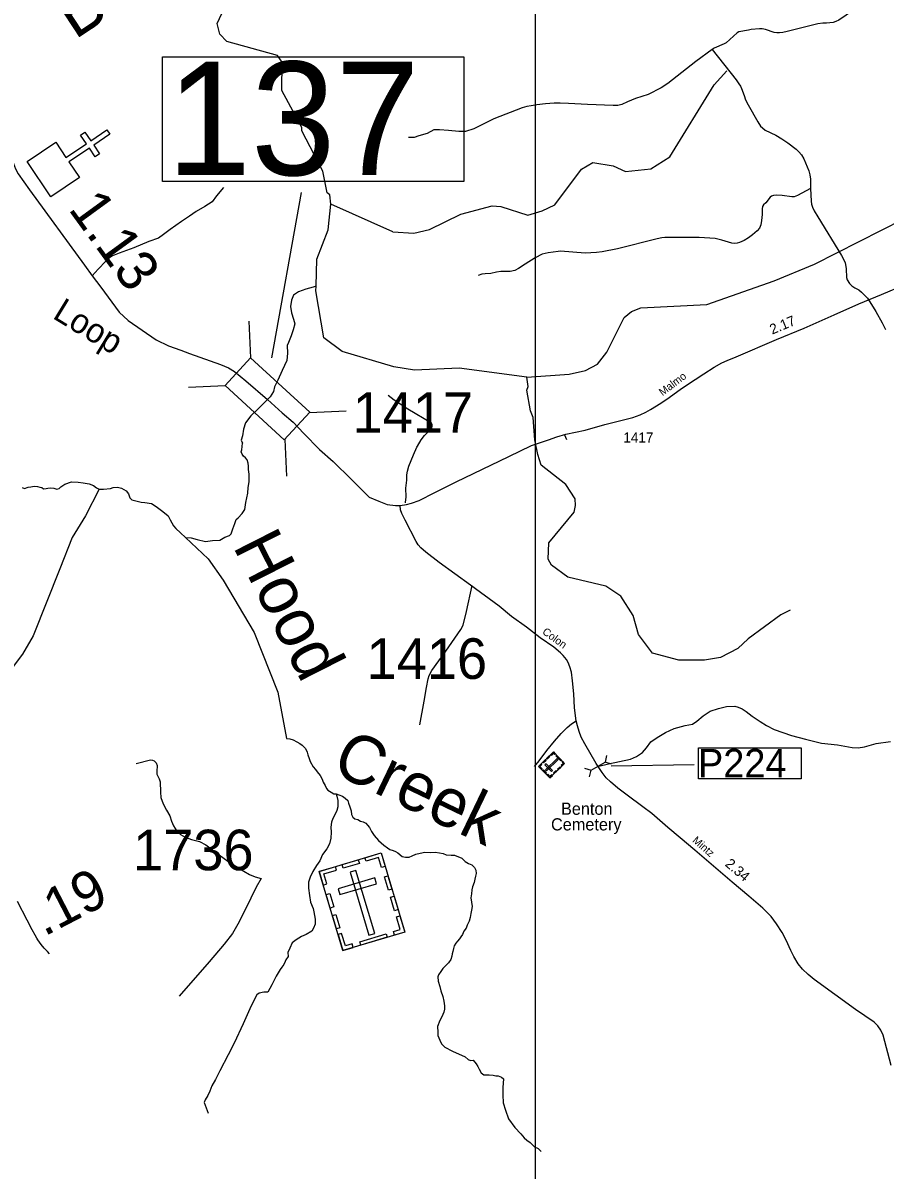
# Model space of a CAD drawing. Extents: x 2225501 to 2309677, y 165449 to 227696.
# Drawn here: x 2259935 to 2270573, y 174218 to 188364 of the extents above; entities that cross this region are included whole.
import ezdxf

# ---------------------------------------------------------------- set-up
doc = ezdxf.new("R2010")
doc.units = 0
for name, color, linetype in [('E_RDY_CMT_EOP', 7, 'Continuous'), ('Exist Vegetation Text', 7, 'Continuous'), ('MARK ENDS WORD SYMBOL CELL', 7, 'Continuous'), ('Old_Level_3', 7, 'Continuous'), ('Old_Level_33', 7, 'Continuous'), ('Old_Level_44', 7, 'Continuous'), ('Old_Level_50', 7, 'Continuous'), ('Old_Level_52', 7, 'Continuous'), ('P_HYD_Drainage_Notes_Label', 7, 'Continuous'), ('P_HYD_Endwall_838_01_18_Dia_Single-Top_CELL', 7, 'Continuous'), ('P_HYD_Pipe_Pipe_Removal', 7, 'Continuous'), ('P_RDY_Dimension_Text', 7, 'Continuous'), ('Prop Mkg Solid Yellow Edge Line', 7, 'Continuous'), ('Prop Support', 7, 'Continuous'), ('Scratch_Level_1', 7, 'Continuous'), ('Scratch_Level_5', 7, 'Continuous'), ('Typical Terminator CELL', 7, 'Continuous')]:
    doc.layers.add(name, color=color, linetype=linetype)

msp = doc.modelspace()

# ---------------------------------------------------------------- linework, layer by layer
at = {"layer": 'Old_Level_3'}
msp.add_line((2266619, 183285), (2266640, 183226), dxfattribs=at)
for points in [[(2270185, 188522), (2270002, 188399), (2269966, 188382), (2269933, 188370), (2269852, 188360), (2269806, 188361), (2269743, 188354), (2269364, 188259), (2269312, 188248), (2269271, 188244), (2269236, 188243), (2269204, 188247), (2269098, 188282), (2269058, 188292), (2269023, 188292), (2268922, 188285), (2268888, 188277), (2268768, 188255), (2268746, 188244), (2268612, 188120), (2268587, 188105), (2268464, 188053), (2268438, 188037)], [(2268438, 188037), (2268237, 187889), (2267893, 187617), (2267810, 187562), (2267648, 187483), (2267494, 187433), (2267393, 187391), (2267324, 187357), (2267274, 187347), (2267216, 187347), (2266900, 187358), (2266666, 187372), (2266562, 187375), (2266488, 187373), (2266382, 187366), (2266276, 187355), (2266204, 187344), (2266152, 187332), (2266096, 187316), (2265745, 187180), (2265497, 187058), (2265394, 187027), (2265315, 187026), (2265185, 187038), (2265073, 187044), (2265005, 187044), (2264924, 187001), (2264818, 186970), (2264762, 186951), (2264694, 186951)], [(2268438, 188037), (2268737, 187662), (2268770, 187615), (2268788, 187585), (2268803, 187555), (2268836, 187468), (2268851, 187416), (2268882, 187355), (2269002, 187143), (2269037, 187093), (2269059, 187070), (2269093, 187042), (2269225, 186979), (2269299, 186936), (2269374, 186885), (2269477, 186807), (2269510, 186776), (2269541, 186736), (2269570, 186687), (2269632, 186542), (2269645, 186490), (2269651, 186438), (2269652, 186324)], [(2262409, 186335), (2262325, 186232), (2262271, 186159), (2262179, 186100), (2262074, 186040), (2261990, 185983), (2261890, 185916), (2261752, 185818), (2261671, 185756), (2261609, 185710), (2261490, 185667), (2261303, 185589), (2261122, 185526), (2261041, 185491), (2261006, 185472), (2260957, 185426), (2260863, 185326), (2260791, 185246)], [(2269652, 186324), (2269492, 186235), (2269452, 186221), (2269422, 186220), (2269302, 186235), (2269234, 186241), (2269198, 186236), (2269172, 186228), (2269154, 186214), (2269101, 186146), (2269074, 186120), (2269062, 186102), (2269057, 186072), (2269056, 186000), (2269049, 185928), (2269038, 185873), (2269023, 185835), (2268995, 185801), (2268935, 185750), (2268889, 185715), (2268836, 185683), (2268778, 185657), (2268746, 185648), (2268710, 185644), (2268680, 185647), (2268559, 185685), (2268477, 185704), (2268278, 185720), (2267923, 185720), (2267855, 185717), (2267819, 185714), (2267759, 185703), (2267271, 185580), (2267080, 185541), (2267014, 185532), (2266874, 185525), (2266568, 185548), (2266538, 185547), (2266416, 185529), (2266342, 185511), (2266255, 185467), (2266132, 185388), (2266048, 185335), (2266004, 185313), (2265947, 185300), (2265881, 185300), (2265833, 185300), (2265780, 185291), (2265710, 185273), (2265640, 185269), (2265596, 185265), (2265552, 185251)], [(2269652, 186324), (2269659, 186168), (2269665, 186128), (2269678, 186091), (2269699, 186049), (2269744, 185972), (2270035, 185497), (2270082, 185410), (2270092, 185330), (2270097, 185224), (2270104, 185196), (2270133, 185149), (2270161, 185123), (2270198, 185098), (2270247, 185071), (2270281, 185045), (2270320, 185009), (2270354, 184970), (2270385, 184925)], [(2270385, 184925), (2270457, 184806), (2270535, 184666), (2270577, 184582)], [(2264657, 182447), (2264657, 182449), (2264662, 182521), (2264660, 182629), (2264670, 182726), (2264671, 182790), (2264679, 182836), (2264698, 182898), (2264754, 183039), (2264796, 183134), (2264802, 183144), (2264848, 183224), (2264890, 183275), (2264891, 183277), (2264982, 183372), (2264985, 183390), (2264985, 183406), (2264981, 183420), (2264975, 183430), (2264685, 183603), (2264514, 183712), (2264441, 183770)], [(2264832, 179710), (2264885, 179999), (2264913, 180169), (2264935, 180276), (2264948, 180318), (2264981, 180379), (2265155, 180617), (2265336, 180884), (2265366, 180937), (2265409, 181105), (2265477, 181425)], [(2267041, 179197), (2267160, 179227), (2267433, 179286), (2267506, 179318), (2267578, 179369), (2267630, 179424), (2267683, 179497), (2267760, 179553), (2267865, 179613), (2267972, 179665), (2268105, 179700), (2268195, 179717), (2268252, 179752), (2268329, 179820), (2268416, 179878), (2268517, 179908), (2268615, 179933), (2268719, 179938), (2268761, 179928), (2268811, 179907), (2268858, 179874), (2268933, 179814), (2269030, 179748), (2269108, 179701), (2269206, 179651), (2269418, 179575), (2269589, 179530), (2269788, 179484), (2269984, 179460), (2270167, 179428), (2270239, 179423), (2270319, 179438), (2270462, 179479), (2270638, 179501)], [(2266247, 179195), (2266305, 179263), (2266399, 179390), (2266493, 179506), (2266575, 179600), (2266649, 179675), (2266702, 179720), (2266762, 179759)], [(2261331, 179233), (2261509, 179275), (2261533, 179273), (2261553, 179264), (2261577, 179240), (2261592, 179208), (2261586, 179132), (2261589, 179098), (2261617, 179044), (2261630, 179005), (2261631, 178877), (2261638, 178811), (2261667, 178733), (2261706, 178655), (2261747, 178588), (2261768, 178520), (2261794, 178461), (2261833, 178399), (2261880, 178357), (2261938, 178322), (2262014, 178293), (2262113, 178270), (2262193, 178229), (2262310, 178139), (2262461, 178028), (2262659, 177903), (2262731, 177862), (2262800, 177832), (2262876, 177813), (2262811, 177707), (2262680, 177437), (2262585, 177252), (2262522, 177137), (2262416, 177002), (2262234, 176786), (2261863, 176362)]]:
    msp.add_lwpolyline(points, dxfattribs=at)
at = {"layer": 'Old_Level_33'}
for points in [[(2259355, 188119), (2259430, 187933), (2259522, 187620), (2259608, 187337), (2259668, 187105), (2259737, 186885), (2259808, 186664), (2259842, 186567), (2259875, 186505), (2260016, 186307), (2260694, 185377), (2260791, 185246), (2260894, 185106), (2261122, 184798), (2261235, 184695), (2261579, 184456), (2261731, 184382), (2261883, 184329), (2261988, 184289), (2262373, 184152), (2262470, 184111), (2262544, 184064), (2262687, 183949), (2262952, 183720)], [(2264588, 182415), (2264667, 182427), (2264730, 182441), (2264825, 182475), (2265019, 182572), (2265282, 182704), (2265496, 182807), (2265931, 183017), (2266208, 183154), (2266420, 183225), (2266522, 183259), (2266633, 183294), (2266872, 183343), (2267113, 183412), (2267461, 183498), (2267549, 183533), (2267619, 183564), (2267679, 183599), (2267804, 183676), (2267910, 183747), (2268062, 183855), (2268230, 183968), (2268338, 184037), (2268465, 184119), (2268560, 184171), (2268623, 184202), (2268735, 184246), (2269234, 184459), (2269573, 184600), (2269943, 184763), (2270248, 184899), (2270530, 185015), (2270820, 185139)], [(2262952, 183720), (2263135, 183554), (2263271, 183439), (2263399, 183302), (2263596, 183104), (2263761, 182956), (2263988, 182733), (2264207, 182516), (2264326, 182465), (2264428, 182427), (2264532, 182413), (2264588, 182415)], [(2270647, 175508), (2270551, 175883), (2270522, 175944), (2270484, 175997), (2270437, 176042), (2270208, 176198), (2269698, 176568), (2269623, 176628), (2269554, 176695), (2269501, 176762), (2269445, 176851), (2269410, 176924), (2269351, 177051), (2269301, 177146), (2269235, 177255), (2269166, 177346), (2269064, 177449), (2268893, 177597), (2268687, 177770), (2268225, 178161), (2268045, 178315), (2267892, 178444), (2267693, 178616), (2267584, 178699), (2267392, 178842), (2267276, 178929), (2267184, 179005), (2267131, 179054), (2267082, 179122), (2267006, 179232), (2266868, 179473), (2266824, 179558), (2266797, 179628), (2266777, 179697), (2266762, 179759), (2266741, 179919), (2266731, 180089), (2266716, 180253), (2266702, 180358), (2266684, 180425), (2266664, 180475), (2266640, 180512), (2266601, 180562), (2266569, 180595), (2266484, 180665), (2266318, 180781), (2266147, 180914), (2265965, 181046), (2265810, 181173), (2265456, 181432), (2265070, 181711), (2264908, 181836), (2264845, 181891), (2264813, 181929), (2264788, 181968), (2264651, 182233), (2264608, 182316), (2264594, 182358), (2264588, 182415)]]:
    msp.add_lwpolyline(points, dxfattribs=at)
at = {"layer": 'Old_Level_44'}
for p, q in [((2266945, 179150), (2267117, 179249)), ((2267137, 179330), (2267117, 179249)), ((2267197, 179225), (2267117, 179249)), ((2266865, 179174), (2266945, 179150)), ((2266926, 179069), (2266945, 179150))]:
    msp.add_line(p, q, dxfattribs=at)
at = {"layer": 'Old_Level_50'}
msp.add_lwpolyline([(2260264, 176885), (2260237, 176913), (2260196, 176954), (2260161, 176998), (2260119, 177058), (2260107, 177079), (2260085, 177116), (2260048, 177181), (2259986, 177299), (2259867, 177528)], dxfattribs=at)
at = {"layer": 'Old_Level_52'}
msp.add_line((2267191, 179203), (2268218, 179220), dxfattribs=at)
msp.add_lwpolyline([(2268271, 179425), (2269537, 179425), (2269537, 179041), (2268271, 179041)], close=True, dxfattribs=at)
at = {"layer": 'P_HYD_Drainage_Notes_Label'}
for p, q in [((2262723, 184685), (2262742, 184233)), ((2261977, 183872), (2262429, 183892)), ((2263472, 183561), (2263924, 183581)), ((2263166, 183228), (2263185, 182775))]:
    msp.add_line(p, q, dxfattribs=at)
msp.add_lwpolyline([(2262742, 184233), (2263473, 183563), (2263160, 183222), (2262429, 183892)], close=True, dxfattribs=at)
at = {"layer": 'P_HYD_Endwall_838_01_18_Dia_Single-Top_CELL'}
msp.add_line((2263008, 184233), (2263370, 186275), dxfattribs=at)
msp.add_lwpolyline([(2261658, 187945), (2265374, 187945), (2265374, 186408), (2261658, 186408)], close=True, dxfattribs=at)
at = {"layer": 'P_HYD_Pipe_Pipe_Removal'}
msp.add_lwpolyline([(2266254, 165449), (2309677, 165449), (2309677, 209697), (2266254, 209697)], close=True, dxfattribs=at)
at = {"layer": 'Prop Mkg Solid Yellow Edge Line'}
for points in [[(2266438, 179055), (2266298, 179196), (2266480, 179375), (2266619, 179233)], [(2266389, 179270), (2266358, 179240), (2266350, 179248), (2266381, 179278)], [(2266382, 179153), (2266396, 179140), (2266540, 179282), (2266527, 179295)], [(2266436, 179316), (2266405, 179286), (2266397, 179294), (2266428, 179324)], [(2266503, 179352), (2266495, 179344), (2266479, 179359), (2266451, 179331), (2266443, 179339), (2266480, 179375)], [(2266571, 179266), (2266511, 179327), (2266519, 179335), (2266579, 179274)], [(2266596, 179257), (2266588, 179249), (2266603, 179233), (2266575, 179205), (2266583, 179197), (2266619, 179233)], [(2266329, 179227), (2266337, 179219), (2266314, 179196), (2266343, 179167), (2266335, 179160), (2266298, 179196)], [(2266386, 179107), (2266350, 179144), (2266358, 179152), (2266394, 179115)], [(2266458, 179131), (2266471, 179145), (2266389, 179228), (2266375, 179215)], [(2266469, 179085), (2266461, 179093), (2266438, 179071), (2266410, 179099), (2266402, 179092), (2266438, 179055)], [(2266522, 179137), (2266491, 179107), (2266483, 179115), (2266514, 179145)], [(2266570, 179184), (2266539, 179154), (2266531, 179162), (2266562, 179192)], [(2263591, 177899), (2264354, 178128), (2264647, 177153), (2263884, 176924)], [(2264404, 177962), (2264361, 177949), (2264323, 178072), (2264168, 178026), (2264155, 178068), (2264354, 178128)], [(2263875, 177984), (2264073, 178044), (2264087, 178000), (2263888, 177941)], [(2263641, 177733), (2263684, 177746), (2263647, 177869), (2263803, 177916), (2263790, 177959), (2263591, 177899)], [(2263826, 177685), (2263847, 177614), (2264298, 177749), (2264277, 177821)], [(2264043, 177912), (2263971, 177891), (2264204, 177114), (2264276, 177135)], [(2264444, 177669), (2264395, 177835), (2264438, 177848), (2264488, 177682)], [(2263726, 177449), (2263676, 177615), (2263720, 177628), (2263770, 177462)], [(2264520, 177416), (2264470, 177582), (2264514, 177595), (2264564, 177430)], [(2263804, 177191), (2263754, 177357), (2263797, 177370), (2263847, 177205)], [(2264520, 177115), (2264507, 177159), (2264591, 177184), (2264544, 177339), (2264587, 177352), (2264647, 177153)], [(2264011, 176962), (2263998, 177006), (2263913, 176981), (2263867, 177135), (2263824, 177123), (2263884, 176924)], [(2264091, 177034), (2264416, 177131), (2264429, 177088), (2264104, 176990)]]:
    msp.add_lwpolyline(points, close=True, dxfattribs=at)
at = {"layer": 'Prop Support'}
msp.add_line((2264497, 185790), (2263732, 186131), dxfattribs=at)
for points in [[(2264497, 185790), (2264760, 185773), (2264951, 185815), (2265340, 186005), (2265723, 186109), (2265831, 186100), (2266165, 185995), (2266340, 186048), (2266497, 186123), (2266826, 186560), (2266967, 186645), (2267217, 186604), (2267368, 186533), (2267684, 186566), (2267916, 186712), (2268466, 187600), (2268622, 187774)], [(2266250, 183223), (2266230, 183498), (2266196, 183580), (2266152, 183837), (2266168, 183879), (2266151, 183995)], [(2269403, 181124), (2269287, 181064), (2268882, 180770), (2268758, 180651), (2268543, 180540), (2268343, 180505), (2268026, 180504), (2267701, 180593), (2267532, 180822), (2267463, 181056), (2267311, 181296), (2267126, 181420), (2266659, 181531), (2266458, 181679), (2266415, 181752), (2266422, 181952), (2266735, 182333), (2266751, 182415), (2266750, 182497), (2266632, 182673), (2266330, 182912), (2266287, 183044), (2266250, 183223)]]:
    msp.add_lwpolyline(points, dxfattribs=at)
at = {"layer": 'Scratch_Level_5'}
msp.add_lwpolyline([(2260339, 186893), (2260466, 186704), (2260719, 186875), (2260647, 186981), (2260700, 187016), (2260772, 186910), (2260971, 187045), (2261007, 186992), (2260808, 186857), (2260879, 186751), (2260826, 186715), (2260755, 186821), (2260502, 186651), (2260631, 186460), (2260278, 186221), (2259986, 186654)], close=True, dxfattribs=at)
at = {"layer": 'Typical Terminator CELL'}
msp.add_line((2261877, 182076), (2261939, 182019), dxfattribs=at)
for points in [[(2263732, 186131), (2263723, 186246), (2263689, 186270), (2263637, 186536), (2263375, 187033), (2263375, 187076), (2263129, 187533), (2263135, 187881), (2263076, 187964), (2262450, 188134), (2262366, 188227), (2262331, 188359), (2262446, 188603), (2262669, 188877), (2262676, 188986), (2262625, 189144), (2262457, 189328), (2262455, 189544), (2262644, 189829), (2262693, 189979), (2262707, 190343), (2262829, 190662), (2262827, 190944), (2262750, 191162)], [(2266151, 183995), (2266675, 184034), (2266875, 184079), (2267024, 184155), (2267139, 184303), (2267352, 184732), (2267442, 184806), (2267559, 184850), (2268375, 184893), (2269205, 185182), (2269703, 185388), (2271079, 186090), (2271635, 186305), (2271991, 186567), (2272248, 186703), (2272472, 186745), (2272806, 186683), (2272982, 186525), (2273050, 186409), (2273094, 186169), (2273204, 185960), (2273255, 185903), (2273548, 185783)], [(2263551, 185116), (2263563, 185452), (2263702, 185813), (2263732, 186131)], [(2263551, 185116), (2263518, 185104), (2263471, 185092), (2263426, 185082), (2263337, 185050), (2263273, 185007), (2263248, 184945), (2263238, 184866), (2263247, 184790), (2263272, 184712), (2263291, 184654), (2263270, 184580), (2263243, 184504), (2263212, 184425), (2263196, 184385), (2263198, 184291), (2263191, 184200), (2263132, 184077), (2263082, 183958), (2263038, 183877), (2263028, 183818), (2262985, 183752), (2262928, 183697), (2262837, 183606), (2262747, 183519), (2262680, 183433), (2262657, 183354), (2262642, 183272), (2262629, 183220), (2262646, 183183)], [(2264512, 184122), (2263872, 184314), (2263646, 184480), (2263550, 185062), (2263551, 185116)], [(2266151, 183995), (2265317, 184106), (2264767, 184084), (2264512, 184122)], [(2261939, 182019), (2262011, 182014), (2262083, 181994), (2262186, 181970), (2262275, 181980), (2262365, 181984), (2262426, 182021), (2262482, 182045), (2262506, 182065), (2262524, 182127), (2262548, 182193), (2262566, 182241), (2262590, 182263), (2262638, 182313), (2262674, 182365), (2262686, 182451), (2262708, 182565), (2262712, 182635), (2262728, 182705), (2262726, 182745), (2262726, 182801), (2262720, 182857), (2262718, 182899), (2262714, 182937), (2262700, 182975), (2262682, 182999), (2262658, 183021), (2262640, 183045), (2262628, 183073), (2262634, 183099), (2262646, 183183)], [(2259925, 182637), (2259954, 182621), (2259999, 182641), (2260034, 182645), (2260074, 182651), (2260115, 182649), (2260142, 182641), (2260166, 182635), (2260188, 182619), (2260220, 182621), (2260244, 182625), (2260280, 182633), (2260318, 182627), (2260352, 182613), (2260382, 182621), (2260404, 182645), (2260452, 182677), (2260532, 182703), (2260616, 182701), (2260678, 182691), (2260750, 182681), (2260806, 182661), (2260842, 182633), (2260874, 182613)], [(2260874, 182613), (2260927, 182613), (2261014, 182623), (2261049, 182635), (2261102, 182641), (2261151, 182627), (2261209, 182593), (2261237, 182557), (2261255, 182509), (2261279, 182485), (2261329, 182469), (2261395, 182453), (2261439, 182451), (2261521, 182437), (2261579, 182401), (2261661, 182341), (2261727, 182287), (2261753, 182235), (2261793, 182163), (2261823, 182130), (2261877, 182076)], [(2260874, 182613), (2260706, 182286), (2260544, 182017), (2260389, 181633), (2260063, 180807), (2259931, 180580), (2259338, 179801), (2258945, 178939), (2258648, 178538), (2258028, 178052), (2257338, 177786), (2256682, 177563)], [(2261939, 182019), (2262222, 181756), (2262406, 181493), (2262788, 180847), (2263078, 180110), (2263186, 179540), (2263227, 179537), (2263271, 179523), (2263315, 179499), (2263350, 179479), (2263382, 179457), (2263420, 179415), (2263440, 179371), (2263450, 179339), (2263466, 179295), (2263478, 179255), (2263514, 179191), (2263544, 179157), (2263566, 179129), (2263602, 179083), (2263626, 179037), (2263640, 179003), (2263666, 178961), (2263682, 178923), (2263696, 178903), (2263740, 178879), (2263770, 178859), (2263798, 178857)], [(2263798, 178857), (2263808, 178828), (2263820, 178774), (2263822, 178716), (2263822, 178696), (2263808, 178652), (2263790, 178616), (2263758, 178552), (2263742, 178508), (2263732, 178448), (2263739, 178384), (2263735, 178310), (2263717, 178240), (2263685, 178179), (2263633, 178108), (2263599, 178030), (2263559, 177974), (2263513, 177898), (2263479, 177828), (2263459, 177770), (2263457, 177696), (2263471, 177602), (2263482, 177520), (2263516, 177445), (2263523, 177402), (2263539, 177312), (2263539, 177250), (2263522, 177199), (2263498, 177162), (2263431, 177124), (2263373, 177099), (2263307, 177058), (2263257, 177019), (2263230, 176954), (2263205, 176899), (2263208, 176853), (2263180, 176811), (2263170, 176789), (2263155, 176753), (2263129, 176719), (2263110, 176691), (2263058, 176608), (2263007, 176504), (2262956, 176412), (2262909, 176411), (2262851, 176398), (2262822, 176377), (2262751, 176245), (2262653, 176023), (2262540, 175782), (2262467, 175640), (2262365, 175443), (2262309, 175336), (2262267, 175258), (2262239, 175192), (2262217, 175138), (2262185, 175083), (2262170, 175049), (2262219, 174918)], [(2263798, 178857), (2263834, 178845), (2263876, 178829), (2263912, 178802), (2263944, 178776), (2263950, 178744), (2263968, 178696), (2263984, 178646), (2263990, 178602), (2264004, 178568), (2264030, 178548), (2264068, 178540), (2264102, 178522), (2264134, 178512), (2264166, 178494), (2264186, 178472), (2264212, 178442), (2264234, 178392), (2264270, 178344), (2264322, 178280), (2264386, 178224), (2264432, 178192), (2264464, 178172), (2264502, 178158), (2264532, 178146), (2264562, 178128)], [(2264562, 178128), (2264616, 178086), (2264656, 178076), (2264702, 178075), (2264738, 178093), (2264784, 178114), (2264838, 178126), (2264892, 178137), (2264960, 178134), (2265022, 178136), (2265074, 178131), (2265120, 178121), (2265158, 178106), (2265220, 178101), (2265259, 178099), (2265351, 178062), (2265392, 178021), (2265434, 177999), (2265474, 177980), (2265505, 177948), (2265523, 177918), (2265527, 177876), (2265520, 177842), (2265512, 177804), (2265503, 177764), (2265483, 177710), (2265472, 177674), (2265468, 177624), (2265463, 177574), (2265471, 177522), (2265476, 177466), (2265470, 177422), (2265461, 177380), (2265455, 177332), (2265440, 177288), (2265416, 177237), (2265403, 177199), (2265375, 177163), (2265358, 177121), (2265338, 177094), (2265322, 177068), (2265298, 177042), (2265277, 177014), (2265257, 176982), (2265247, 176949), (2265240, 176915), (2265232, 176883), (2265226, 176855), (2265213, 176815), (2265187, 176775), (2265153, 176741), (2265116, 176704), (2265092, 176666), (2265063, 176626), (2265053, 176601), (2265059, 176548), (2265078, 176480), (2265091, 176426), (2265116, 176358), (2265130, 176300), (2265137, 176243), (2265137, 176203), (2265128, 176163), (2265102, 176106), (2265077, 176064), (2265050, 175988), (2265054, 175920), (2265055, 175878), (2265078, 175820), (2265098, 175774), (2265139, 175733), (2265237, 175684), (2265392, 175614), (2265429, 175582), (2265457, 175569), (2265489, 175571), (2265527, 175529), (2265546, 175494), (2265566, 175460), (2265589, 175416), (2265621, 175393), (2265689, 175391), (2265735, 175386), (2265769, 175378), (2265798, 175379), (2265840, 175365), (2265866, 175343), (2265857, 175237), (2265856, 175147), (2265861, 175045), (2265890, 174958), (2265928, 174848), (2266005, 174743), (2266080, 174664), (2266121, 174615), (2266151, 174585), (2266193, 174557), (2266248, 174506), (2266294, 174483), (2266331, 174447)]]:
    msp.add_lwpolyline(points, dxfattribs=at)

# ---------------------------------------------------------------- texts
at = {"layer": 'E_RDY_CMT_EOP'}
for s, height, p in [('1417', 500, (2264003, 183310)), ('1417', 125, (2267343, 183189)), ('1416', 500, (2264175, 180275)), ('1736', 500, (2261293, 177915))]:
    msp.add_text(s, height=height, dxfattribs=at).set_placement(p)
at = {"layer": 'Exist Vegetation Text'}
for s, p in [('Benton', (2266574, 178599)), ('Cemetery', (2266451, 178406))]:
    msp.add_text(s, height=150, dxfattribs=at).set_placement(p)
at = {"layer": 'MARK ENDS WORD SYMBOL CELL'}
for s, height, rotation, p in [('Loop', 300, 328.6195, (2260288, 184730)), ('Malmo', 95, 37.1583, (2267827, 183760)), ('Colon', 95, 324.0798, (2266335, 180838)), ('Mintz', 95, 318.8275, (2268188, 178271))]:
    msp.add_text(s, height=height, rotation=rotation, dxfattribs=at).set_placement(p)
at = {"layer": 'Old_Level_52'}
msp.add_text('P224', height=350, dxfattribs=at).set_placement((2268264, 179061))
at = {"layer": 'P_HYD_Endwall_838_01_18_Dia_Single-Top_CELL'}
msp.add_text('137', height=1400, dxfattribs=at).set_placement((2261708, 186487))
at = {"layer": 'P_RDY_Dimension_Text'}
for s, height, rotation, p in [('1.13', 500, 306.0655, (2260486, 186069)), ('2.17', 125, 22.5761, (2269180, 184520)), ('2.34', 125, 319.3862, (2268589, 177978)), ('.19', 500, 27.4362, (2260196, 177093))]:
    msp.add_text(s, height=height, rotation=rotation, dxfattribs=at).set_placement(p)
at = {"layer": 'Scratch_Level_1'}
for s, rotation, p in [('Br.', 33.3601, (2260575, 188152)), ('Hood', 296.8781, (2262519, 181914)), ('Creek', 334.3458, (2263721, 179134))]:
    msp.add_text(s, height=600, rotation=rotation, dxfattribs=at).set_placement(p)

doc.saveas('drawing.dxf')
